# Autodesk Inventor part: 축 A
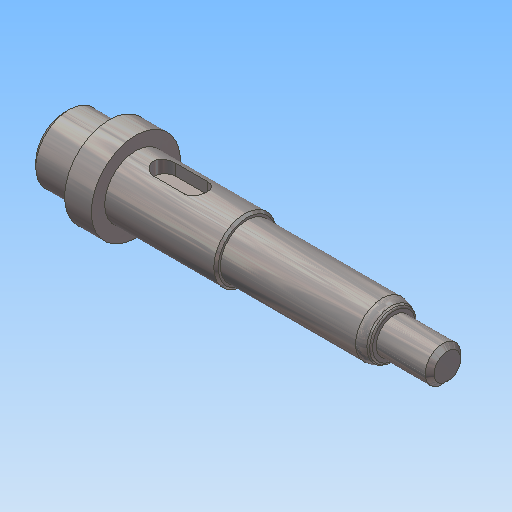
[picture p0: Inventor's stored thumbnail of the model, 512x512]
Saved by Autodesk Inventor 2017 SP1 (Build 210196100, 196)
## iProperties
Created: 2020-04
Part Number: 축 A
Material: 강철, 연강
Document SubType Name: Modeling
Designer: mduedu
Density: 7.86 g/cm^3
Mass: 91.1355 g
Surface Area: 41.2026 cm^2
Volume: 11.5948 cm^3
Appearance: 강철
Author: mduedu
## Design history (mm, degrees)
sketch "스케치1"
  geometry: L1 (0, 0)-(10, 0); L2 (10, 0)-(10, 7.5); L3 (10, 7.5)-(0, 7.5); L4 (0, 7.5)-(0, 0); L5 (10, 0)-(16, 0); L6 (16, 0)-(16, 10); L7 (16, 10)-(10, 10); L8 (10, 10)-(10, 0); L9 (16, 0)-(41, 0); L10 (41, 0)-(41, 7); L11 (41, 7)-(16, 7); L12 (16, 7)-(16, 0); L13 (41, 0)-(74, 0); L14 (74, 0)-(74, 6); L15 (74, 6)-(41, 6); L16 (41, 6)-(41, 0); L17 (74, 0)-(86, 0); L18 (86, 0)-(86, 4); L19 (86, 4)-(74, 4); L20 (74, 4)-(74, 0)
  constraints: 40 end point, 10 parallel, 5 horizontal, 5 perpendicular
  dimensions: "d0" = 86 distance between parallel lines of L18 L4; "d2" = 10 distance of L2.end L3.end; "d3" = 6 distance of L6.end L7.end; "d4" = 12 distance of L18.end L19.end; "d5" = 8 diameter of L19 L17; "d6" = 12 diameter of L15 L13; "d7" = 14 diameter of L11 L9; "d8" = 15 diameter of L3 L1; "d9" = 20 diameter of L7 L5; "d10" = 45 distance between parallel lines of L10 L18
revolve "회전1" sketch "스케치1" stored, may be unused: angle "d11" = 90 deg
sketch "스케치2"
  geometry: L1 (0, -7.5)-(0, 7.5) reference; L2 (0, 7.5)-(10, 7.5) reference; L3 (10, 7.5)-(10, 10) reference; L4 (10, 10)-(16, 10) reference; L5 (16, 10)-(16, 7) reference; L6 (16, 7)-(41, 7) reference; L7 (41, 7)-(41, 6) reference; L8 (41, 6)-(74, 6) reference; L9 (74, 6)-(74, 4) reference; L10 (74, 4)-(86, 4) reference; L11 (86, 4)-(86, -4) reference; L12 (86, -4)-(74, -4) reference; L13 (74, -4)-(74, -6) reference; L14 (74, -6)-(41, -6) reference; L15 (41, -6)-(41, -7) reference; L16 (41, -7)-(16, -7) reference; L17 (16, -7)-(16, -10) reference; L18 (16, -10)-(10, -10) reference; L19 (10, -10)-(10, -7.5) reference; L20 (10, -7.5)-(0, -7.5) reference; L21 (86, -4)-(78, -4); L22 (78, -4)-(78, -2.8); L23 (78, -2.8)-(86, -2.8); L24 (86, -2.8)-(86, -4); 1 further point
  constraints: 8 end point, 2 parallel, 1 horizontal, 1 perpendicular
  dimensions: "d12" = 8 distance of L22.end L23.end; "d13" = 1.2 distance of L21.end L22.end
extrude "돌출1" cut sketch "스케치2" stored distance "d14" = 2; taper "d15" = 0 deg
fillet "모깎기1" dims "d16" = 1
sketch "스케치3"
  geometry: L1 (0, -7.5)-(0, 7.5) reference; L2 (0, 7.5)-(10, 7.5) reference; L3 (10, 7.5)-(10, 10) reference; L4 (10, 10)-(16, 10) reference; L5 (16, 10)-(16, 7) reference; L6 (16, 7)-(41, 7) reference; L7 (41, 7)-(41, 6) reference; L8 (41, 6)-(74, 6) reference; L9 (74, 6)-(74, 4) reference; L10 (74, 4)-(86, 4) reference; L11 (86, 4)-(86, -2.8) reference; L12 (86, -2.8)-(78, -2.8) reference; L13 (78, -2.8)-(78, -4) reference; L14 (78, -4)-(74, -4) reference; L15 (74, -4)-(74, -6) reference; L16 (74, -6)-(41, -6) reference; L17 (41, -6)-(41, -7) reference; L18 (41, -7)-(16, -7) reference; L19 (16, -7)-(16, -10) reference; L20 (16, -10)-(10, -10) reference; L21 (10, -10)-(10, -7.5) reference; L22 (10, -7.5)-(0, -7.5) reference; L23 (20, 7)-(32, 7); L24 (32, 7)-(32, 4); L25 (32, 4)-(20, 4); L26 (20, 4)-(20, 7); 1 further point
  constraints: 8 end point, 2 parallel, 1 horizontal, 1 perpendicular, 1 point on line
  dimensions: "d17" = 12 distance of L24.end L25.end; "d18" = 3 distance of L23.end L24.end; "d19" = 4 distance from line of L26 L4.end
extrude "돌출2" cut sketch "스케치3" stored distance "d20" = 5; taper "d21" = 0 deg
fillet "모깎기2" dims "d22" = 2.5
chamfer "모따기1" distance "d23" = 1; stored, may be unused: second distance "d24" = 2, angle "d25" = 45 deg
chamfer "모따기2" distance "d26" = 0.5; stored, may be unused: second distance "d27" = 2, angle "d28" = 45 deg
fillet "모깎기3" dims "d29" = 0.3
chamfer "모따기3" distance "d30" = 1.56; stored, may be unused: second distance "d31" = 2, angle "d32" = 30 deg
fillet "모깎기4" dims "d33" = 4, "d34" = 0.5
node "솔리드1"
node "절단 모서리 투영1"
node "절단 모서리 투영2"
